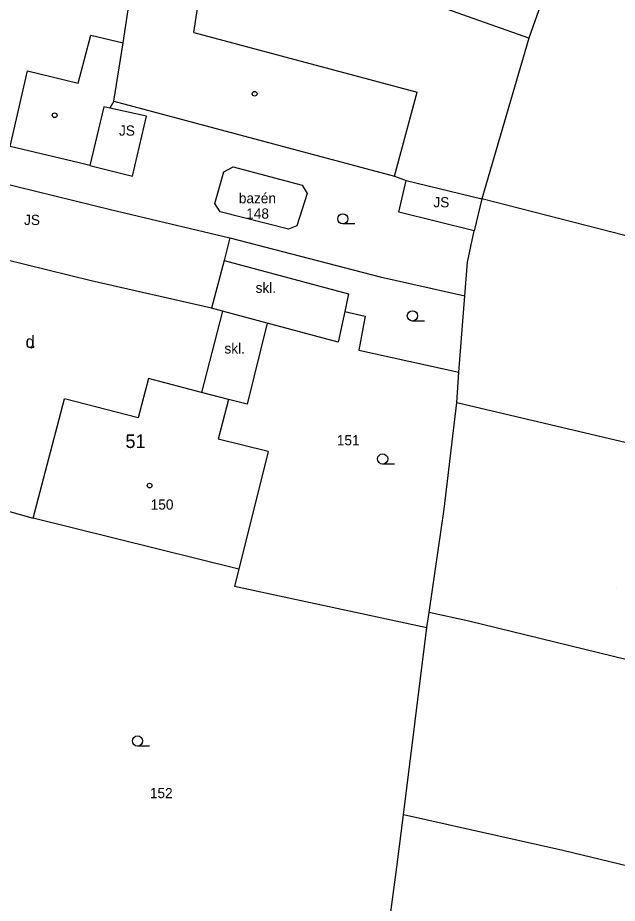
# Model space of a CAD drawing. Extents: x -836739 to -835945, y -1070775 to -1070126.
# Drawn here: x -836621.5 to -836577.4, y -1070514.1 to -1070449 of the extents above; entities that cross this region are included whole.
import ezdxf

# ---------------------------------------------------------------- set-up
doc = ezdxf.new("R2010")
doc.units = 0
for name, color, linetype in [('BodPole_mer', 7, 'Continuous'), ('Budovy_hranice', 7, 'Continuous'), ('Budovy_kody', 7, 'Continuous'), ('OstPloch_kody', 7, 'Continuous'), ('RuianAdr_popis', 7, 'Continuous'), ('RuianPar_popis', 7, 'Continuous'), ('Stavby_hr_stav', 7, 'Continuous'), ('Stavby_kody', 7, 'Continuous'), ('Stavby_linie', 7, 'Continuous'), ('Vodstvo_hranice', 7, 'Continuous'), ('Vodstvo_kody', 7, 'Continuous')]:
    doc.layers.add(name, color=color, linetype=linetype)

msp = doc.modelspace()

# ---------------------------------------------------------------- linework, layer by layer
at = {"layer": 'BodPole_mer'}
for p, q in [((-836616.09, -1070450.28), (-836616.09, -1070450.28)), ((-836608.53, -1070450.08), (-836608.53, -1070450.08)), ((-836613.73, -1070450.82), (-836613.73, -1070450.82)), ((-836583.91, -1070450.49), (-836583.91, -1070450.49)), ((-836620.76, -1070452.9), (-836620.76, -1070452.9)), ((-836617.02, -1070453.79), (-836617.02, -1070453.79)), ((-836592.12, -1070454.46), (-836592.12, -1070454.46)), ((-836615.15, -1070455.54), (-836615.15, -1070455.54)), ((-836614.4, -1070455.13), (-836614.4, -1070455.13)), ((-836614.71, -1070455.64), (-836614.71, -1070455.64)), ((-836612.02, -1070456.22), (-836612.02, -1070456.22)), ((-836616.95, -1070459.66), (-836616.95, -1070459.66)), ((-836616.17, -1070459.86), (-836616.17, -1070459.86)), ((-836605.63, -1070459.94), (-836605.63, -1070459.94)), ((-836613.04, -1070460.63), (-836613.04, -1070460.63)), ((-836606.32, -1070460.31), (-836606.32, -1070460.31)), ((-836593.77, -1070460.64), (-836593.77, -1070460.64)), ((-836600.56, -1070461.3), (-836600.56, -1070461.3)), ((-836592.91, -1070460.96), (-836592.91, -1070460.96)), ((-836600.2, -1070461.91), (-836600.2, -1070461.91)), ((-836606.98, -1070462.64), (-836606.98, -1070462.64)), ((-836587.35, -1070462.31), (-836587.35, -1070462.31)), ((-836614.56, -1070463.12), (-836614.56, -1070463.12)), ((-836606.6, -1070463.26), (-836606.6, -1070463.26)), ((-836593.47, -1070463.29), (-836593.47, -1070463.29)), ((-836601.58, -1070464.53), (-836601.58, -1070464.53)), ((-836600.96, -1070464.29), (-836600.96, -1070464.29)), ((-836587.92, -1070464.66), (-836587.92, -1070464.66)), ((-836605.88, -1070465.16), (-836605.88, -1070465.16)), ((-836606.31, -1070466.85), (-836606.31, -1070466.85)), ((-836588.41, -1070466.95), (-836588.41, -1070466.95)), ((-836616.08, -1070468.33), (-836616.08, -1070468.33)), ((-836594.82, -1070468.03), (-836594.82, -1070468.03)), ((-836597.17, -1070469.3), (-836597.17, -1070469.3)), ((-836588.62, -1070469.44), (-836588.62, -1070469.44)), ((-836607.22, -1070470.35), (-836607.22, -1070470.35)), ((-836606.43, -1070470.56), (-836606.43, -1070470.56)), ((-836597.44, -1070470.6), (-836597.44, -1070470.6)), ((-836595.93, -1070470.94), (-836595.93, -1070470.94)), ((-836603.14, -1070471.45), (-836603.14, -1070471.45)), ((-836597.91, -1070472.85), (-836597.91, -1070472.85)), ((-836596.39, -1070473.44), (-836596.39, -1070473.44)), ((-836589.04, -1070475.06), (-836589.04, -1070475.06)), ((-836611.85, -1070475.52), (-836611.85, -1070475.52)), ((-836618.03, -1070477), (-836618.03, -1070477)), ((-836607.97, -1070476.54), (-836607.97, -1070476.54)), ((-836605.97, -1070477.06), (-836605.97, -1070477.06)), ((-836604.62, -1070477.4), (-836604.62, -1070477.4)), ((-836589.2, -1070477.29), (-836589.2, -1070477.29)), ((-836612.61, -1070478.42), (-836612.61, -1070478.42)), ((-836606.73, -1070479.97), (-836606.73, -1070479.97)), ((-836603.06, -1070480.88), (-836603.06, -1070480.88)), ((-836590.13, -1070485.13), (-836590.13, -1070485.13)), ((-836620.34, -1070485.79), (-836620.34, -1070485.79)), ((-836605.21, -1070489.55), (-836605.21, -1070489.55)), ((-836605.54, -1070490.79), (-836605.54, -1070490.79)), ((-836591.23, -1070492.73), (-836591.23, -1070492.73)), ((-836591.39, -1070493.82), (-836591.39, -1070493.82)), ((-836588.31, -1070493.37), (-836588.31, -1070493.37)), ((-836593.12, -1070507.61), (-836593.12, -1070507.61)), ((-836581.41, -1070510.24), (-836581.41, -1070510.24)), ((-836593.6, -1070511.46), (-836593.6, -1070511.46))]:
    msp.add_line(p, q, dxfattribs=at)
at = {"layer": 'Budovy_hranice'}
for p, q in [((-836608.53, -1070450.08), (-836607.85, -1070445.7)), ((-836583.91, -1070450.49), (-836591.18, -1070447.92)), ((-836608.53, -1070450.08), (-836592.12, -1070454.46)), ((-836593.77, -1070460.64), (-836592.12, -1070454.46)), ((-836614.4, -1070455.13), (-836593.77, -1070460.64)), ((-836611.85, -1070475.52), (-836612.61, -1070478.42)), ((-836620.34, -1070485.79), (-836618.03, -1070477)), ((-836612.61, -1070478.42), (-836618.03, -1070477)), ((-836605.97, -1070477.06), (-836606.73, -1070479.97)), ((-836603.06, -1070480.88), (-836606.73, -1070479.97)), ((-836603.06, -1070480.88), (-836605.21, -1070489.55)), ((-836605.21, -1070489.55), (-836620.34, -1070485.79))]:
    msp.add_line(p, q, dxfattribs=at)
for points in [[(-836579.2, -1070437.18), (-836582.9, -1070447.63), (-836583.91, -1070450.49)], [(-836614.4, -1070455.13), (-836613.73, -1070450.82), (-836612.88, -1070445.29), (-836612.82, -1070444.93)], [(-836616.17, -1070459.86), (-836616.95, -1070459.66), (-836622.02, -1070458.45), (-836620.76, -1070452.9), (-836617.02, -1070453.79), (-836616.09, -1070450.28), (-836613.73, -1070450.82)], [(-836614.4, -1070455.13), (-836614.71, -1070455.64), (-836615.15, -1070455.54), (-836616.17, -1070459.86)], [(-836605.97, -1070477.06), (-836607.97, -1070476.54), (-836611.85, -1070475.52)]]:
    msp.add_lwpolyline(points, dxfattribs=at)
at = {"layer": 'Budovy_kody'}
for centre in [(-836604.06, -1070454.58), (-836618.76, -1070456.16), (-836611.78, -1070483.39)]:
    msp.add_circle(centre, 0.175, dxfattribs=at)
at = {"layer": 'OstPloch_kody'}
for p, q in [((-836596.705, -1070464.15), (-836597.58, -1070464.15)), ((-836591.585, -1070471.29), (-836592.46, -1070471.29)), ((-836593.775, -1070481.81), (-836594.65, -1070481.81)), ((-836611.795, -1070502.55), (-836612.67, -1070502.55))]:
    msp.add_line(p, q, dxfattribs=at)
msp.add_lwpolyline([(-836620.519, -1070473.26), (-836620.519, -1070473.265), (-836620.518, -1070473.271), (-836620.51, -1070473.275), (-836620.493, -1070473.273), (-836620.463, -1070473.264), (-836620.415, -1070473.243), (-836620.347, -1070473.207), (-836620.254, -1070473.154)], dxfattribs=at)
for centre in [(-836597.58, -1070463.775), (-836592.46, -1070470.915), (-836594.65, -1070481.435), (-836612.67, -1070502.175)]:
    msp.add_ellipse(centre, major_axis=(0.375, 0), ratio=0.999999, dxfattribs=at)
at = {"layer": 'RuianAdr_popis'}
msp.add_line((-836613.56, -1070480.63), (-836613.56, -1070480.63), dxfattribs=at)
at = {"layer": 'RuianPar_popis'}
for p, q in [((-836604.68, -1070463.76), (-836604.68, -1070463.76)), ((-836598.02, -1070480.43), (-836598.02, -1070480.43)), ((-836611.7, -1070485.16), (-836611.7, -1070485.16)), ((-836577.44, -1070490.89), (-836577.44, -1070490.89)), ((-836611.76, -1070506.38), (-836611.76, -1070506.38))]:
    msp.add_line(p, q, dxfattribs=at)
at = {"layer": 'Stavby_hr_stav'}
msp.add_line((-836606.43, -1070470.56), (-836607.97, -1070476.54), dxfattribs=at)
for points in [[(-836616.17, -1070459.86), (-836613.04, -1070460.63), (-836612.02, -1070456.22), (-836614.71, -1070455.64)], [(-836626.37, -1070475.52), (-836624.25, -1070466.62), (-836623.9, -1070465.13), (-836622.96, -1070461.05), (-836614.56, -1070463.12), (-836605.88, -1070465.16), (-836606.31, -1070466.85), (-836607.22, -1070470.35), (-836616.08, -1070468.33), (-836622.44, -1070466.77), (-836624.62, -1070475.89), (-836626.37, -1070475.52)], [(-836592.91, -1070460.96), (-836587.35, -1070462.31), (-836587.92, -1070464.66), (-836593.47, -1070463.29), (-836592.91, -1070460.96)], [(-836606.31, -1070466.85), (-836597.17, -1070469.3), (-836597.44, -1070470.6), (-836597.91, -1070472.85), (-836603.14, -1070471.45), (-836606.43, -1070470.56), (-836607.22, -1070470.35)], [(-836603.14, -1070471.45), (-836604.62, -1070477.4), (-836605.97, -1070477.06)]]:
    msp.add_lwpolyline(points, dxfattribs=at)
at = {"layer": 'Stavby_linie'}
for p, q in [((-836583.91, -1070450.49), (-836587.35, -1070462.31)), ((-836593.77, -1070460.64), (-836592.91, -1070460.96)), ((-836573.73, -1070465.81), (-836587.35, -1070462.31))]:
    msp.add_line(p, q, dxfattribs=at)
for points in [[(-836588.62, -1070469.44), (-836588.41, -1070466.95), (-836587.92, -1070464.66)], [(-836605.88, -1070465.16), (-836594.82, -1070468.03), (-836588.62, -1070469.44)], [(-836589.2, -1070477.29), (-836589.04, -1070475.06), (-836588.62, -1070469.44)], [(-836597.44, -1070470.6), (-836595.93, -1070470.94), (-836596.39, -1070473.44), (-836589.04, -1070475.06)], [(-836595.23, -1070523.53), (-836593.6, -1070511.46), (-836593.12, -1070507.61), (-836591.39, -1070493.82), (-836591.23, -1070492.73), (-836590.13, -1070485.13), (-836589.2, -1070477.29)], [(-836589.2, -1070477.29), (-836575.47, -1070480.52), (-836565.48, -1070483.09)], [(-836624.4, -1070485.49), (-836624.35, -1070484.67), (-836620.34, -1070485.79)], [(-836605.21, -1070489.55), (-836605.54, -1070490.79), (-836591.39, -1070493.82)], [(-836571.36, -1070497.51), (-836588.31, -1070493.37), (-836591.23, -1070492.73)], [(-836570.33, -1070512.89), (-836581.41, -1070510.24), (-836593.12, -1070507.61)]]:
    msp.add_lwpolyline(points, dxfattribs=at)
at = {"layer": 'Vodstvo_hranice'}
msp.add_lwpolyline([(-836606.32, -1070460.31), (-836605.63, -1070459.94), (-836600.56, -1070461.3), (-836600.2, -1070461.91), (-836600.96, -1070464.29), (-836601.58, -1070464.53), (-836606.6, -1070463.26), (-836606.98, -1070462.64), (-836606.32, -1070460.31)], dxfattribs=at)

# ---------------------------------------------------------------- texts
at = {"layer": 'OstPloch_kody'}
msp.add_text('d', height=0.9, dxfattribs=at).set_placement((-836620.895, -1070473.26))
at = {"layer": 'RuianAdr_popis'}
msp.add_text('51', height=1, dxfattribs=at).set_placement((-836613.56, -1070480.63))
at = {"layer": 'RuianPar_popis'}
for s, p in [('148', (-836604.68, -1070463.76)), ('151', (-836598.02, -1070480.43)), ('150', (-836611.7, -1070485.16)), ('152', (-836611.76, -1070506.38))]:
    msp.add_text(s, height=0.75, dxfattribs=at).set_placement(p)
at = {"layer": 'Stavby_kody'}
for s, p in [('JS', (-836614.03, -1070457.66)), ('JS', (-836590.92, -1070462.93)), ('JS', (-836621.01, -1070464.23)), ('skl.', (-836603.99, -1070469.22)), ('skl.', (-836606.28, -1070473.68))]:
    msp.add_text(s, height=0.75, dxfattribs=at).set_placement(p)
at = {"layer": 'Vodstvo_kody'}
msp.add_text('bazén', height=0.75, dxfattribs=at).set_placement((-836605.22, -1070462.63))

doc.saveas('drawing.dxf')
